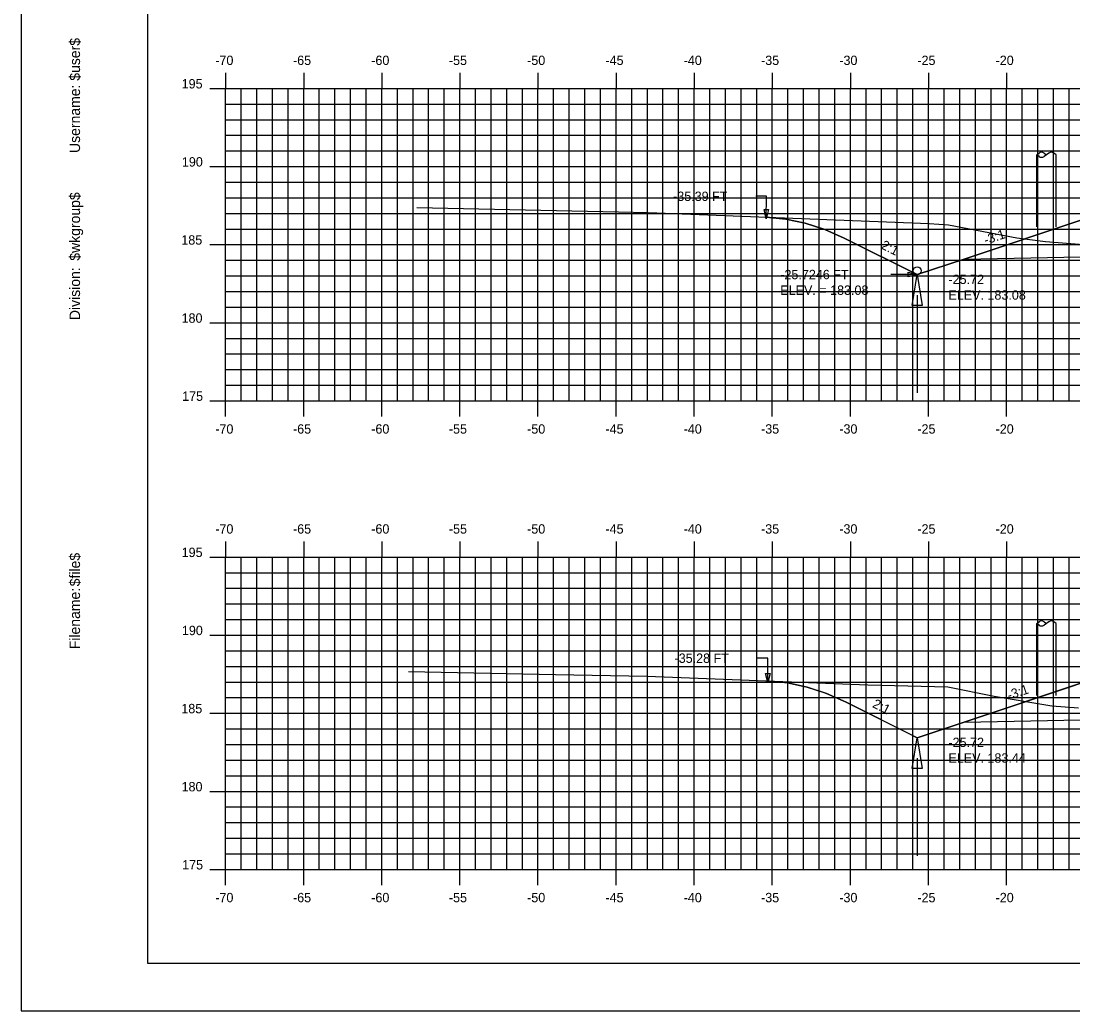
# Model space of a CAD drawing. Extents: x 1139650 to 1139820, y 608981 to 609091.
# Drawn here: x 1139650.1 to 1139717.5, y 608981.3 to 609044.6 of the extents above; entities that cross this region are included whole.
import ezdxf

# ---------------------------------------------------------------- set-up
doc = ezdxf.new("R2010")
doc.units = 0
for name, color, linetype in [('ANNOTATION', 7, 'Continuous'), ('BORDER', 7, 'Continuous'), ('D_Drainage_Culvert', 7, 'Continuous'), ('D_Drainage_Ditch_Line', 7, 'Continuous'), ('D_Roadway_SlopeLines', 7, 'Continuous'), ('D_Roadway_SubGrade', 7, 'Continuous'), ('D_Text_Standard', 7, 'Continuous'), ('H_V ANNOTATION', 7, 'Continuous'), ('MAJOR', 7, 'Continuous'), ('MINOR', 7, 'Continuous'), ('PLOT BOUNDARY', 7, 'Continuous'), ('S_Roadway_Centerline', 7, 'Continuous'), ('S_Utilities_Pole_StreetLight', 7, 'Continuous')]:
    doc.layers.add(name, color=color, linetype=linetype)

msp = doc.modelspace()

# ---------------------------------------------------------------- linework, layer by layer
for points in [[(1139697.827, 609032.096), (1139699.077, 609031.975), (1139700.327, 609031.71), (1139701.577, 609031.3), (1139702.827, 609030.747), (1139707.494, 609028.414), (1139710.494, 609029.414), (1139718.217, 609031.989), (1139718.218, 609031.989), (1139722.218, 609032.149), (1139733.218, 609032.369), (1139744.218, 609032.149), (1139748.218, 609031.989)], [(1139697.94, 609002.397), (1139699.008, 609002.294), (1139699.19, 609002.276), (1139700.258, 609002.05), (1139700.44, 609002.011), (1139701.508, 609001.661), (1139701.69, 609001.602), (1139702.758, 609001.129), (1139702.94, 609001.049), (1139706.832, 608999.103), (1139707.494, 608998.772), (1139707.931, 608998.918), (1139710.494, 608999.772), (1139717.091, 609001.971), (1139718.217, 609002.346)]]:
    msp.add_lwpolyline(points)
at = {"layer": 'BORDER'}
msp.add_lwpolyline([(1139658.219, 608984.335), (1139818.219, 608984.335), (1139818.219, 609089.335), (1139658.219, 609089.335)], close=True, dxfattribs=at)
at = {"layer": 'D_Drainage_Culvert'}
msp.add_circle((1139707.494, 609028.664), 0.25, dxfattribs=at)
at = {"layer": 'D_Drainage_Ditch_Line'}
for p, q in [((1139707.494, 609027.102), (1139707.493, 609020.858)), ((1139707.494, 608997.46), (1139707.493, 608991.216))]:
    msp.add_line(p, q, dxfattribs=at)
for points in [[(1139707.822, 609026.446), (1139707.166, 609026.446), (1139707.494, 609028.414)], [(1139707.822, 608996.804), (1139707.166, 608996.804), (1139707.494, 608998.772)]]:
    msp.add_lwpolyline(points, close=True, dxfattribs=at)
at = {"layer": 'D_Roadway_SlopeLines'}
for points in [[(1139707.494, 609028.414), (1139702.827, 609030.747), (1139701.577, 609031.3), (1139700.327, 609031.71), (1139699.077, 609031.975), (1139697.827, 609032.096)], [(1139710.494, 609029.414), (1139707.494, 609028.414)], [(1139707.494, 608998.772), (1139702.94, 609001.049), (1139701.69, 609001.602), (1139700.44, 609002.011), (1139699.19, 609002.276), (1139697.94, 609002.397)], [(1139710.494, 608999.772), (1139707.494, 608998.772)]]:
    msp.add_lwpolyline(points, dxfattribs=at)
at = {"layer": 'D_Roadway_SubGrade'}
for points in [[(1139722.218, 609031.732), (1139722.218, 609031.899), (1139718.218, 609031.739), (1139718.218, 609031.989), (1139718.217, 609031.989), (1139710.494, 609029.414), (1139722.218, 609029.649)], [(1139722.218, 609002.09), (1139722.218, 609002.257), (1139718.218, 609002.097), (1139718.218, 609002.347), (1139718.217, 609002.347), (1139710.494, 608999.772), (1139722.218, 609000.007)]]:
    msp.add_lwpolyline(points, close=True, dxfattribs=at)
at = {"layer": 'D_Text_Standard'}
for points in [[(1139697.827, 609031.997), (1139697.853, 609033.431), (1139697.173, 609033.431)], [(1139707.494, 609028.414), (1139706.483, 609028.421), (1139705.803, 609028.421)], [(1139697.94, 609002.299), (1139697.933, 609003.86), (1139697.254, 609003.86)]]:
    msp.add_lwpolyline(points, dxfattribs=at)
for points in [[(1139697.827, 609031.997), (1139697.692, 609032.582), (1139697.983, 609032.577)], [(1139707.494, 609028.414), (1139706.911, 609028.273), (1139706.913, 609028.564)], [(1139697.94, 609002.299), (1139697.792, 609002.88), (1139698.083, 609002.881)]]:
    msp.add_lwpolyline(points, close=True, dxfattribs=at)
at = {"layer": 'MAJOR'}
for p, q in [((1139663.218, 609041.337), (1139663.218, 609040.335)), ((1139668.218, 609041.337), (1139668.218, 609040.335)), ((1139673.218, 609041.337), (1139673.218, 609040.335)), ((1139678.218, 609041.337), (1139678.218, 609040.335)), ((1139683.218, 609041.337), (1139683.218, 609040.335)), ((1139688.218, 609041.337), (1139688.218, 609040.335)), ((1139693.218, 609041.337), (1139693.218, 609040.335)), ((1139698.218, 609041.337), (1139698.218, 609040.335)), ((1139703.218, 609041.337), (1139703.218, 609040.335)), ((1139708.218, 609041.337), (1139708.218, 609040.335)), ((1139713.218, 609041.337), (1139713.218, 609040.335)), ((1139662.216, 609040.335), (1139663.218, 609040.335)), ((1139663.218, 609040.335), (1139803.218, 609040.335)), ((1139663.218, 609020.335), (1139663.218, 609040.335)), ((1139663.218, 609020.335), (1139663.218, 609040.335)), ((1139663.218, 609040.335), (1139803.218, 609040.335)), ((1139668.218, 609020.335), (1139668.218, 609040.335)), ((1139673.218, 609020.335), (1139673.218, 609040.335)), ((1139678.218, 609020.335), (1139678.218, 609040.335)), ((1139683.218, 609020.335), (1139683.218, 609040.335)), ((1139688.218, 609020.335), (1139688.218, 609040.335)), ((1139693.218, 609020.335), (1139693.218, 609040.335)), ((1139698.218, 609020.335), (1139698.218, 609040.335)), ((1139703.218, 609020.335), (1139703.218, 609040.335)), ((1139708.218, 609020.335), (1139708.218, 609040.335)), ((1139713.218, 609020.335), (1139713.218, 609040.335)), ((1139662.216, 609035.335), (1139663.218, 609035.335)), ((1139663.218, 609035.335), (1139803.218, 609035.335)), ((1139662.216, 609030.335), (1139663.218, 609030.335)), ((1139663.218, 609030.335), (1139803.218, 609030.335)), ((1139662.216, 609025.335), (1139663.218, 609025.335)), ((1139663.218, 609025.335), (1139803.218, 609025.335)), ((1139662.216, 609020.335), (1139663.218, 609020.335)), ((1139663.218, 609020.335), (1139803.218, 609020.335)), ((1139663.218, 609020.335), (1139803.218, 609020.335)), ((1139663.218, 609019.333), (1139663.218, 609020.335)), ((1139668.218, 609019.333), (1139668.218, 609020.335)), ((1139673.218, 609019.333), (1139673.218, 609020.335)), ((1139678.218, 609019.333), (1139678.218, 609020.335)), ((1139683.218, 609019.333), (1139683.218, 609020.335)), ((1139688.218, 609019.333), (1139688.218, 609020.335)), ((1139693.218, 609019.333), (1139693.218, 609020.335)), ((1139698.218, 609019.333), (1139698.218, 609020.335)), ((1139703.218, 609019.333), (1139703.218, 609020.335)), ((1139708.218, 609019.333), (1139708.218, 609020.335)), ((1139713.218, 609019.333), (1139713.218, 609020.335)), ((1139663.218, 609011.337), (1139663.218, 609010.335)), ((1139668.218, 609011.337), (1139668.218, 609010.335)), ((1139673.218, 609011.337), (1139673.218, 609010.335)), ((1139678.218, 609011.337), (1139678.218, 609010.335)), ((1139683.218, 609011.337), (1139683.218, 609010.335)), ((1139688.218, 609011.337), (1139688.218, 609010.335)), ((1139693.218, 609011.337), (1139693.218, 609010.335)), ((1139698.218, 609011.337), (1139698.218, 609010.335)), ((1139703.218, 609011.337), (1139703.218, 609010.335)), ((1139708.218, 609011.337), (1139708.218, 609010.335)), ((1139713.218, 609011.337), (1139713.218, 609010.335)), ((1139662.216, 609010.335), (1139663.218, 609010.335)), ((1139663.218, 609010.335), (1139803.218, 609010.335)), ((1139663.218, 608990.335), (1139663.218, 609010.335)), ((1139663.218, 608990.335), (1139663.218, 609010.335)), ((1139663.218, 609010.335), (1139803.218, 609010.335)), ((1139668.218, 608990.335), (1139668.218, 609010.335)), ((1139673.218, 608990.335), (1139673.218, 609010.335)), ((1139678.218, 608990.335), (1139678.218, 609010.335)), ((1139683.218, 608990.335), (1139683.218, 609010.335)), ((1139688.218, 608990.335), (1139688.218, 609010.335)), ((1139693.218, 608990.335), (1139693.218, 609010.335)), ((1139698.218, 608990.335), (1139698.218, 609010.335)), ((1139703.218, 608990.335), (1139703.218, 609010.335)), ((1139708.218, 608990.335), (1139708.218, 609010.335)), ((1139713.218, 608990.335), (1139713.218, 609010.335)), ((1139662.216, 609005.335), (1139663.218, 609005.335)), ((1139663.218, 609005.335), (1139803.218, 609005.335)), ((1139662.216, 609000.335), (1139663.218, 609000.335)), ((1139663.218, 609000.335), (1139803.218, 609000.335)), ((1139662.216, 608995.335), (1139663.218, 608995.335)), ((1139663.218, 608995.335), (1139803.218, 608995.335)), ((1139662.216, 608990.335), (1139663.218, 608990.335)), ((1139663.218, 608990.335), (1139803.218, 608990.335)), ((1139663.218, 608990.335), (1139803.218, 608990.335)), ((1139663.218, 608989.333), (1139663.218, 608990.335)), ((1139668.218, 608989.333), (1139668.218, 608990.335)), ((1139673.218, 608989.333), (1139673.218, 608990.335)), ((1139678.218, 608989.333), (1139678.218, 608990.335)), ((1139683.218, 608989.333), (1139683.218, 608990.335)), ((1139688.218, 608989.333), (1139688.218, 608990.335)), ((1139693.218, 608989.333), (1139693.218, 608990.335)), ((1139698.218, 608989.333), (1139698.218, 608990.335)), ((1139703.218, 608989.333), (1139703.218, 608990.335)), ((1139708.218, 608989.333), (1139708.218, 608990.335)), ((1139713.218, 608989.333), (1139713.218, 608990.335))]:
    msp.add_line(p, q, dxfattribs=at)
at = {"layer": 'MINOR'}
for p, q in [((1139664.218, 609020.335), (1139664.218, 609040.335)), ((1139665.218, 609020.335), (1139665.218, 609040.335)), ((1139666.218, 609020.335), (1139666.218, 609040.335)), ((1139667.218, 609020.335), (1139667.218, 609040.335)), ((1139669.218, 609020.335), (1139669.218, 609040.335)), ((1139670.218, 609020.335), (1139670.218, 609040.335)), ((1139671.218, 609020.335), (1139671.218, 609040.335)), ((1139672.218, 609020.335), (1139672.218, 609040.335)), ((1139674.218, 609020.335), (1139674.218, 609040.335)), ((1139675.218, 609020.335), (1139675.218, 609040.335)), ((1139676.218, 609020.335), (1139676.218, 609040.335)), ((1139677.218, 609020.335), (1139677.218, 609040.335)), ((1139679.218, 609020.335), (1139679.218, 609040.335)), ((1139680.218, 609020.335), (1139680.218, 609040.335)), ((1139681.218, 609020.335), (1139681.218, 609040.335)), ((1139682.218, 609020.335), (1139682.218, 609040.335)), ((1139684.218, 609020.335), (1139684.218, 609040.335)), ((1139685.218, 609020.335), (1139685.218, 609040.335)), ((1139686.218, 609020.335), (1139686.218, 609040.335)), ((1139687.218, 609020.335), (1139687.218, 609040.335)), ((1139689.218, 609020.335), (1139689.218, 609040.335)), ((1139690.218, 609020.335), (1139690.218, 609040.335)), ((1139691.218, 609020.335), (1139691.218, 609040.335)), ((1139692.218, 609020.335), (1139692.218, 609040.335)), ((1139694.218, 609020.335), (1139694.218, 609040.335)), ((1139695.218, 609020.335), (1139695.218, 609040.335)), ((1139696.218, 609020.335), (1139696.218, 609040.335)), ((1139697.218, 609020.335), (1139697.218, 609040.335)), ((1139699.218, 609020.335), (1139699.218, 609040.335)), ((1139700.218, 609020.335), (1139700.218, 609040.335)), ((1139701.218, 609020.335), (1139701.218, 609040.335)), ((1139702.218, 609020.335), (1139702.218, 609040.335)), ((1139704.218, 609020.335), (1139704.218, 609040.335)), ((1139705.218, 609020.335), (1139705.218, 609040.335)), ((1139706.218, 609020.335), (1139706.218, 609040.335)), ((1139707.218, 609020.335), (1139707.218, 609040.335)), ((1139709.218, 609020.335), (1139709.218, 609040.335)), ((1139710.218, 609020.335), (1139710.218, 609040.335)), ((1139711.218, 609020.335), (1139711.218, 609040.335)), ((1139712.218, 609020.335), (1139712.218, 609040.335)), ((1139714.218, 609020.335), (1139714.218, 609040.335)), ((1139715.218, 609020.335), (1139715.218, 609040.335)), ((1139716.218, 609020.335), (1139716.218, 609040.335)), ((1139717.218, 609020.335), (1139717.218, 609040.335)), ((1139663.218, 609039.335), (1139803.218, 609039.335)), ((1139663.218, 609039.335), (1139664.22, 609039.335)), ((1139663.218, 609038.335), (1139803.218, 609038.335)), ((1139663.218, 609038.335), (1139664.22, 609038.335)), ((1139663.218, 609037.335), (1139803.218, 609037.335)), ((1139663.218, 609037.335), (1139664.22, 609037.335)), ((1139663.218, 609036.335), (1139803.218, 609036.335)), ((1139663.218, 609036.335), (1139664.22, 609036.335)), ((1139663.218, 609034.335), (1139803.218, 609034.335)), ((1139663.218, 609034.335), (1139664.22, 609034.335)), ((1139663.218, 609033.335), (1139803.218, 609033.335)), ((1139663.218, 609033.335), (1139664.22, 609033.335)), ((1139663.218, 609032.335), (1139803.218, 609032.335)), ((1139663.218, 609032.335), (1139664.22, 609032.335)), ((1139663.218, 609031.335), (1139803.218, 609031.335)), ((1139663.218, 609031.335), (1139664.22, 609031.335)), ((1139663.218, 609029.335), (1139803.218, 609029.335)), ((1139663.218, 609029.335), (1139664.22, 609029.335)), ((1139663.218, 609028.335), (1139803.218, 609028.335)), ((1139663.218, 609028.335), (1139664.22, 609028.335)), ((1139663.218, 609027.335), (1139803.218, 609027.335)), ((1139663.218, 609027.335), (1139664.22, 609027.335)), ((1139663.218, 609026.335), (1139803.218, 609026.335)), ((1139663.218, 609026.335), (1139664.22, 609026.335)), ((1139663.218, 609024.335), (1139803.218, 609024.335)), ((1139663.218, 609024.335), (1139664.22, 609024.335)), ((1139663.218, 609023.335), (1139803.218, 609023.335)), ((1139663.218, 609023.335), (1139664.22, 609023.335)), ((1139663.218, 609022.335), (1139803.218, 609022.335)), ((1139663.218, 609022.335), (1139664.22, 609022.335)), ((1139663.218, 609021.335), (1139803.218, 609021.335)), ((1139663.218, 609021.335), (1139664.22, 609021.335)), ((1139664.218, 608990.335), (1139664.218, 609010.335)), ((1139665.218, 608990.335), (1139665.218, 609010.335)), ((1139666.218, 608990.335), (1139666.218, 609010.335)), ((1139667.218, 608990.335), (1139667.218, 609010.335)), ((1139669.218, 608990.335), (1139669.218, 609010.335)), ((1139670.218, 608990.335), (1139670.218, 609010.335)), ((1139671.218, 608990.335), (1139671.218, 609010.335)), ((1139672.218, 608990.335), (1139672.218, 609010.335)), ((1139674.218, 608990.335), (1139674.218, 609010.335)), ((1139675.218, 608990.335), (1139675.218, 609010.335)), ((1139676.218, 608990.335), (1139676.218, 609010.335)), ((1139677.218, 608990.335), (1139677.218, 609010.335)), ((1139679.218, 608990.335), (1139679.218, 609010.335)), ((1139680.218, 608990.335), (1139680.218, 609010.335)), ((1139681.218, 608990.335), (1139681.218, 609010.335)), ((1139682.218, 608990.335), (1139682.218, 609010.335)), ((1139684.218, 608990.335), (1139684.218, 609010.335)), ((1139685.218, 608990.335), (1139685.218, 609010.335)), ((1139686.218, 608990.335), (1139686.218, 609010.335)), ((1139687.218, 608990.335), (1139687.218, 609010.335)), ((1139689.218, 608990.335), (1139689.218, 609010.335)), ((1139690.218, 608990.335), (1139690.218, 609010.335)), ((1139691.218, 608990.335), (1139691.218, 609010.335)), ((1139692.218, 608990.335), (1139692.218, 609010.335)), ((1139694.218, 608990.335), (1139694.218, 609010.335)), ((1139695.218, 608990.335), (1139695.218, 609010.335)), ((1139696.218, 608990.335), (1139696.218, 609010.335)), ((1139697.218, 608990.335), (1139697.218, 609010.335)), ((1139699.218, 608990.335), (1139699.218, 609010.335)), ((1139700.218, 608990.335), (1139700.218, 609010.335)), ((1139701.218, 608990.335), (1139701.218, 609010.335)), ((1139702.218, 608990.335), (1139702.218, 609010.335)), ((1139704.218, 608990.335), (1139704.218, 609010.335)), ((1139705.218, 608990.335), (1139705.218, 609010.335)), ((1139706.218, 608990.335), (1139706.218, 609010.335)), ((1139707.218, 608990.335), (1139707.218, 609010.335)), ((1139709.218, 608990.335), (1139709.218, 609010.335)), ((1139710.218, 608990.335), (1139710.218, 609010.335)), ((1139711.218, 608990.335), (1139711.218, 609010.335)), ((1139712.218, 608990.335), (1139712.218, 609010.335)), ((1139714.218, 608990.335), (1139714.218, 609010.335)), ((1139715.218, 608990.335), (1139715.218, 609010.335)), ((1139716.218, 608990.335), (1139716.218, 609010.335)), ((1139717.218, 608990.335), (1139717.218, 609010.335)), ((1139663.218, 609009.335), (1139803.218, 609009.335)), ((1139663.218, 609009.335), (1139664.22, 609009.335)), ((1139663.218, 609008.335), (1139803.218, 609008.335)), ((1139663.218, 609008.335), (1139664.22, 609008.335)), ((1139663.218, 609007.335), (1139803.218, 609007.335)), ((1139663.218, 609007.335), (1139664.22, 609007.335)), ((1139663.218, 609006.335), (1139803.218, 609006.335)), ((1139663.218, 609006.335), (1139664.22, 609006.335)), ((1139663.218, 609004.335), (1139803.218, 609004.335)), ((1139663.218, 609004.335), (1139664.22, 609004.335)), ((1139663.218, 609003.335), (1139803.218, 609003.335)), ((1139663.218, 609003.335), (1139664.22, 609003.335)), ((1139663.218, 609002.335), (1139803.218, 609002.335)), ((1139663.218, 609002.335), (1139664.22, 609002.335)), ((1139663.218, 609001.335), (1139803.218, 609001.335)), ((1139663.218, 609001.335), (1139664.22, 609001.335)), ((1139663.218, 608999.335), (1139803.218, 608999.335)), ((1139663.218, 608999.335), (1139664.22, 608999.335)), ((1139663.218, 608998.335), (1139803.218, 608998.335)), ((1139663.218, 608998.335), (1139664.22, 608998.335)), ((1139663.218, 608997.335), (1139803.218, 608997.335)), ((1139663.218, 608997.335), (1139664.22, 608997.335)), ((1139663.218, 608996.335), (1139803.218, 608996.335)), ((1139663.218, 608996.335), (1139664.22, 608996.335)), ((1139663.218, 608994.335), (1139803.218, 608994.335)), ((1139663.218, 608994.335), (1139664.22, 608994.335)), ((1139663.218, 608993.335), (1139803.218, 608993.335)), ((1139663.218, 608993.335), (1139664.22, 608993.335)), ((1139663.218, 608992.335), (1139803.218, 608992.335)), ((1139663.218, 608992.335), (1139664.22, 608992.335)), ((1139663.218, 608991.335), (1139803.218, 608991.335)), ((1139663.218, 608991.335), (1139664.22, 608991.335))]:
    msp.add_line(p, q, dxfattribs=at)
at = {"layer": 'PLOT BOUNDARY'}
msp.add_lwpolyline([(1139650.125, 608981.276), (1139820.125, 608981.276), (1139820.125, 609091.276), (1139650.125, 609091.276)], close=True, dxfattribs=at)
at = {"layer": 'S_Roadway_Centerline'}
for points in [[(1139675.462, 609032.703), (1139688.369, 609032.428), (1139690.273, 609032.394), (1139708.269, 609031.684), (1139709.502, 609031.606), (1139713.88, 609030.773), (1139715.7, 609030.526), (1139718.142, 609030.349)], [(1139674.929, 609003.009), (1139684.331, 609002.809), (1139690.216, 609002.702), (1139704.335, 609002.145), (1139709.46, 609002.021), (1139712.426, 609001.421), (1139716.116, 609000.81), (1139717.82, 609000.683)]]:
    msp.add_lwpolyline(points, dxfattribs=at)
at = {"layer": 'S_Utilities_Pole_StreetLight'}
for p, q in [((1139715.144, 609036.088), (1139715.3, 609036.198)), ((1139715.144, 609031.468), (1139715.148, 609036.088)), ((1139715.3, 609035.977), (1139715.144, 609036.088)), ((1139715.613, 609036.198), (1139715.77, 609036.088)), ((1139715.77, 609036.088), (1139715.613, 609035.977)), ((1139715.926, 609036.198), (1139715.77, 609036.088)), ((1139716.394, 609036.088), (1139716.238, 609036.198)), ((1139716.394, 609031.468), (1139716.398, 609036.088)), ((1139715.144, 609006.088), (1139715.3, 609006.198)), ((1139715.144, 609001.468), (1139715.148, 609006.088)), ((1139715.3, 609005.977), (1139715.144, 609006.088)), ((1139715.613, 609006.198), (1139715.77, 609006.088)), ((1139715.77, 609006.088), (1139715.613, 609005.977)), ((1139715.926, 609006.198), (1139715.77, 609006.088)), ((1139716.394, 609006.088), (1139716.238, 609006.198)), ((1139716.394, 609001.468), (1139716.398, 609006.088))]:
    msp.add_line(p, q, dxfattribs=at)
for centre, start, end in [((1139715.457, 609035.977), 90, 125.26439), ((1139715.457, 609036.198), 234.73561, 270), ((1139715.457, 609035.977), 54.73561, 90), ((1139715.457, 609036.198), 270, 305.26439), ((1139716.082, 609035.977), 90, 125.26439), ((1139716.082, 609035.977), 54.73561, 90), ((1139715.457, 609005.977), 90, 125.26439), ((1139715.457, 609005.977), 54.73561, 90), ((1139716.082, 609005.977), 90, 125.26439), ((1139716.082, 609005.977), 54.73561, 90), ((1139715.457, 609006.198), 234.73561, 270), ((1139715.457, 609006.198), 270, 305.26439)]:
    msp.add_arc(centre, 0.271, start, end, dxfattribs=at)

# ---------------------------------------------------------------- texts
at = {"layer": 'ANNOTATION'}
for s, rotation, p in [('-3:1', 18.43482, (1139711.873, 609030.328)), ('2:1', 333.43495, (1139705.127, 609030.115)), ('-3:1', 18.43478, (1139713.373, 609001.186)), ('2:1', 333.43495, (1139704.582, 609000.746))]:
    msp.add_text(s, height=0.6, rotation=rotation, dxfattribs=at).set_placement(p)
at = {"layer": 'BORDER'}
for s, p in [('$user$', (1139653.903, 609040.827)), ('Username:', (1139653.903, 609036.203)), ('$wkgroup$', (1139653.903, 609029.305)), ('Division:', (1139653.903, 609025.501)), ('$file$', (1139653.903, 609008.461)), ('Filename:', (1139653.903, 609004.433))]:
    msp.add_text(s, height=0.6696, rotation=90, dxfattribs=at).set_placement(p)
at = {"layer": 'D_Text_Standard'}
for s, p in [('-35.39 FT', (1139691.868, 609033.131)), ('-25.7246 FT.', (1139698.729, 609028.121)), ('-25.72', (1139709.494, 609027.814)), ('ELEV. = 183.08', (1139698.729, 609027.121)), ('ELEV. 183.08', (1139709.494, 609026.812)), ('-35.28 FT', (1139691.959, 609003.56)), ('-25.72', (1139709.494, 608998.172)), ('ELEV. 183.44', (1139709.494, 608997.17))]:
    msp.add_text(s, height=0.6, dxfattribs=at).set_placement(p)
at = {"layer": 'H_V ANNOTATION'}
for s, p in [('-70', (1139662.56, 609041.835)), ('-65', (1139667.536, 609041.835)), ('-60', (1139672.544, 609041.835)), ('-50', (1139682.522, 609041.835)), ('-40', (1139692.544, 609041.835)), ('-35', (1139697.498, 609041.835)), ('-30', (1139702.507, 609041.835)), ('-25', (1139707.504, 609041.835)), ('-20', (1139712.512, 609041.835)), ('-55', (1139677.514, 609041.835)), ('-45', (1139687.536, 609041.835)), ('195', (1139660.407, 609040.335)), ('190', (1139660.423, 609035.335)), ('185', (1139660.386, 609030.335)), ('180', (1139660.402, 609025.335)), ('175', (1139660.439, 609020.335)), ('-70', (1139662.56, 609018.235)), ('-65', (1139667.536, 609018.235)), ('-60', (1139672.544, 609018.235)), ('-55', (1139677.514, 609018.235)), ('-50', (1139682.522, 609018.235)), ('-45', (1139687.536, 609018.235)), ('-40', (1139692.544, 609018.235)), ('-35', (1139697.498, 609018.235)), ('-30', (1139702.507, 609018.235)), ('-25', (1139707.504, 609018.235)), ('-20', (1139712.512, 609018.235)), ('-70', (1139662.56, 609011.835)), ('-65', (1139667.536, 609011.835)), ('-60', (1139672.544, 609011.835)), ('-55', (1139677.514, 609011.835)), ('-50', (1139682.522, 609011.835)), ('-45', (1139687.536, 609011.835)), ('-40', (1139692.544, 609011.835)), ('-35', (1139697.498, 609011.835)), ('-30', (1139702.507, 609011.835)), ('-25', (1139707.504, 609011.835)), ('-20', (1139712.512, 609011.835)), ('195', (1139660.407, 609010.335)), ('190', (1139660.423, 609005.335)), ('185', (1139660.386, 609000.335)), ('180', (1139660.402, 608995.335)), ('175', (1139660.439, 608990.335)), ('-70', (1139662.56, 608988.235)), ('-65', (1139667.536, 608988.235)), ('-60', (1139672.544, 608988.235)), ('-55', (1139677.514, 608988.235)), ('-50', (1139682.522, 608988.235)), ('-45', (1139687.536, 608988.235)), ('-40', (1139692.544, 608988.235)), ('-35', (1139697.498, 608988.235)), ('-30', (1139702.507, 608988.235)), ('-25', (1139707.504, 608988.235)), ('-20', (1139712.512, 608988.235))]:
    msp.add_text(s, height=0.6, dxfattribs=at).set_placement(p)
at = {"layer": 'MAJOR'}
for p in [(1139663.214, 609020.335), (1139663.214, 608990.335)]:
    msp.add_text('-', height=0.006, dxfattribs=at).set_placement(p)

doc.saveas('drawing.dxf')
